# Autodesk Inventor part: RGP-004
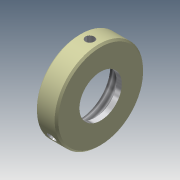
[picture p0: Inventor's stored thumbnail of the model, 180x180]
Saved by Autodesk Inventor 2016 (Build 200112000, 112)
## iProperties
Created: 2013-10
Part Number: RGP-004
Material: Aluminum 6061
Document SubType Name: Modeling
Designer: normanpa
Density: 2.71 g/cm^3
Appearance: 255,255,194
Description: LOCK RING
Mass: 285.24 g
Surface Area: 244.865 cm^2
Volume: 105.255 cm^3
Author: Autodesk
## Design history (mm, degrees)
sketch "Sketch1"
  geometry: L1 (0, 0)-(24, 0); L2 (0, 50)-(24, 50); L3 (0, 50)-(0, 35); L4 (0, 35)-(18, 35); L5 (18, 35)-(18, 24); L6 (18, 24)-(24, 24); L7 (24, 24)-(24, 50)
  constraints: 14 end point, 4 perpendicular, 2 horizontal, 1 parallel, 1 vertical, 1 vertical alignment
  dimensions: "d0" = 24 distance of L2.start L2.end; "d1" = 100 diameter of L2 L1; "d2" = 70 diameter of L4 L1; "d3" = 48 diameter of L6 L1; "d4" = 18 distance between parallel lines of L5 L3
revolve "Revolution1" sketch "Sketch1" stored, may be unused: angle "d5" = 90 deg
thread "Thread1" dims "d6" = 10, "d7" = 0
workplane "Work Plane1"
sketch "Sketch2"
  geometry: L1 (12, 50)-(12, -50) reference; L2 (-12, 50)-(-12, -50) reference; L3 (12, 0)-(-12, 0); 1 further point
  constraints: 2 end point, 2 midpoint
hole "Hole1" sketch "Sketch2" at (0, 0) diameter "d8" = 10; stored, may be unused: countersink angle "d12" = 90 deg, drill point angle "d14" = 0 deg; dims "d9" = 6, "d10" = 4, "d11" = 2, "d13" = 8
pattern_circular "Circular Pattern1" dims angle "d16" = 360 deg
chamfer "Chamfer1" distance "d18" = 2; stored, may be unused: second distance "d19" = 2, angle "d20" = 45 deg
body "Solid1"
